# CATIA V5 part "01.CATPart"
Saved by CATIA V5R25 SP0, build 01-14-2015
Part number: Part1
Bounding box of the stored display mesh (mm): x -14.877 to 14.877, y -14.99 to 14.99, z -108 to 0
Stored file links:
  D:\feridun18052022montaj\01.CATPart
  D:\feridun18052022montaj\cektirme.CATProduct
  D:\feridun18052022montaj\03.CATPart
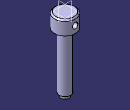
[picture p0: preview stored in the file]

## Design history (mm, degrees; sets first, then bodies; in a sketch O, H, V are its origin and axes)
Body1 (main body)
  Sketch1 on yz-plane, origin (0, 0, 0), H (0, 1, 0), V (0, 0, 1)
    line L1 (0, 0) -> (-15, 0)
    line L2 (-15, 0) -> (-15, -20)
    line L3 (-15, -20) -> (-8, -20)
    line L4 (-8, -20) -> (-8, -100)
    line L5 (-8, -100) -> (-6, -100)
    line L6 (-6, -100) -> (-6, -104.5359)
    axis line L7 (0, -86.8404) -> (0, 7.786)
    line L8 (-6, -104.5359) -> (0, -108)
    point P9 (0, -108)
    length L2 = 20
    radius about axis L2 L7 = 15
    radius about axis L4 L7 = 8
    radius about axis L6 L7 = 6
    distance P9 L5 = 8
    angle L8 L7 = 60
    distance P9 L1 = 108
    horizontal: L1 H, L3 H, L5 H
    vertical: L2 V, L4 V, L6 V, L7 V
    coincidence: L7 V, P9 L7
  Shaft1: profile Sketch1, axis Sketch1.L7, angle 360
  Chamfer1: length 2, angle 45, on edge [face of Shaft1 from Sketch1.L2 | face of Shaft1 from Sketch1.L1]
  Sketch2 on zx-plane, origin (0, 0, 0), H (-1, 0, 0), V (0, 0, 1)
    circle A1 centre (0, -10) radius 4
    point P1 (0, -10)
    radius A1 = 4
    distance H P1 = 10
    coincidence: P1 V
  Pocket1: profile Sketch2, direction (0, -1, 0), through (limit type 6), opposite side through (limit type 6)
  Thread1: diameter 16, depth 70, pitch 1.5, on face of Shaft1 from Sketch1.L4, from face of Shaft1 from Sketch1.L5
